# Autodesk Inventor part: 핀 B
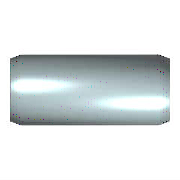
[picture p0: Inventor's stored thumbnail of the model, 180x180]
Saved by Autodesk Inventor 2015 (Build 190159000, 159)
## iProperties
Created: 2012-02
Part Number: 핀 B
Material: 강철, 연강
Description: 평행 핀
Document SubType Name: Modeling
Standard: KS B 1320
Designer: mduedu
Standards Organization: KS
Language: ko-KR
Size Designation: B 4 x  10
Categories: <MemberInstance><Categories><Category DisplayName="조임쇠" InternalName="e4da775c-781d-43d5-af7c-5136215cf5a6" Mnemonic="FSTN"><Category DisplayName="핀" InternalNa
Density: 1 g/cm^3
Appearance: 노란색
IsCustomPart: 1
Author: mduedu
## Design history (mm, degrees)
sketch "스케치"
  geometry: C1 r 2 at (0, 0); 1 further point
  constraints: 1 centre point, 1 coincident
  dimensions: "d1" = 4 diameter of C1 (= NND)
extrude "본체" new body sketch "스케치" distance "d2" = 10 (= NLG); taper "d3" = 0 deg
chamfer "스케치2" distance "d8" = 0.63 (= PHH); stored, may be unused: angle "d9" = 15 deg (= FAWI), second distance "d12" = 0.63 (= PHH)
body "Solid1"
chamfer "모따기1" distance "d4" = 0.63 (= PHH); stored, may be unused: angle "d5" = 15 deg (= FAWI), second distance "d11" = 0.63 (= PHH)
other parameters: "NND" = 4 [user parameter; used in 1 equation term], "NLG" = 10 [user parameter; used in 1 equation term], "PHH" = 0.63 [user parameter; used in 4 equation terms], "FAWI" = 15 deg [user parameter; used in 2 equation terms], "d13" = 0, "d15" = 0, "d16" = 0, "KAH" = 0.5 [user parameter]
